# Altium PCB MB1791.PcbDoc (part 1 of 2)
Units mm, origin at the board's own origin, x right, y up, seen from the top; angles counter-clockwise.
Board outline 68.69 x 34.35 mm, 2 copper layers (Top Layer, Bottom Layer), stack 0.78 mm thick; 94 components, 70 nets, 269 pads, 1128 vias.
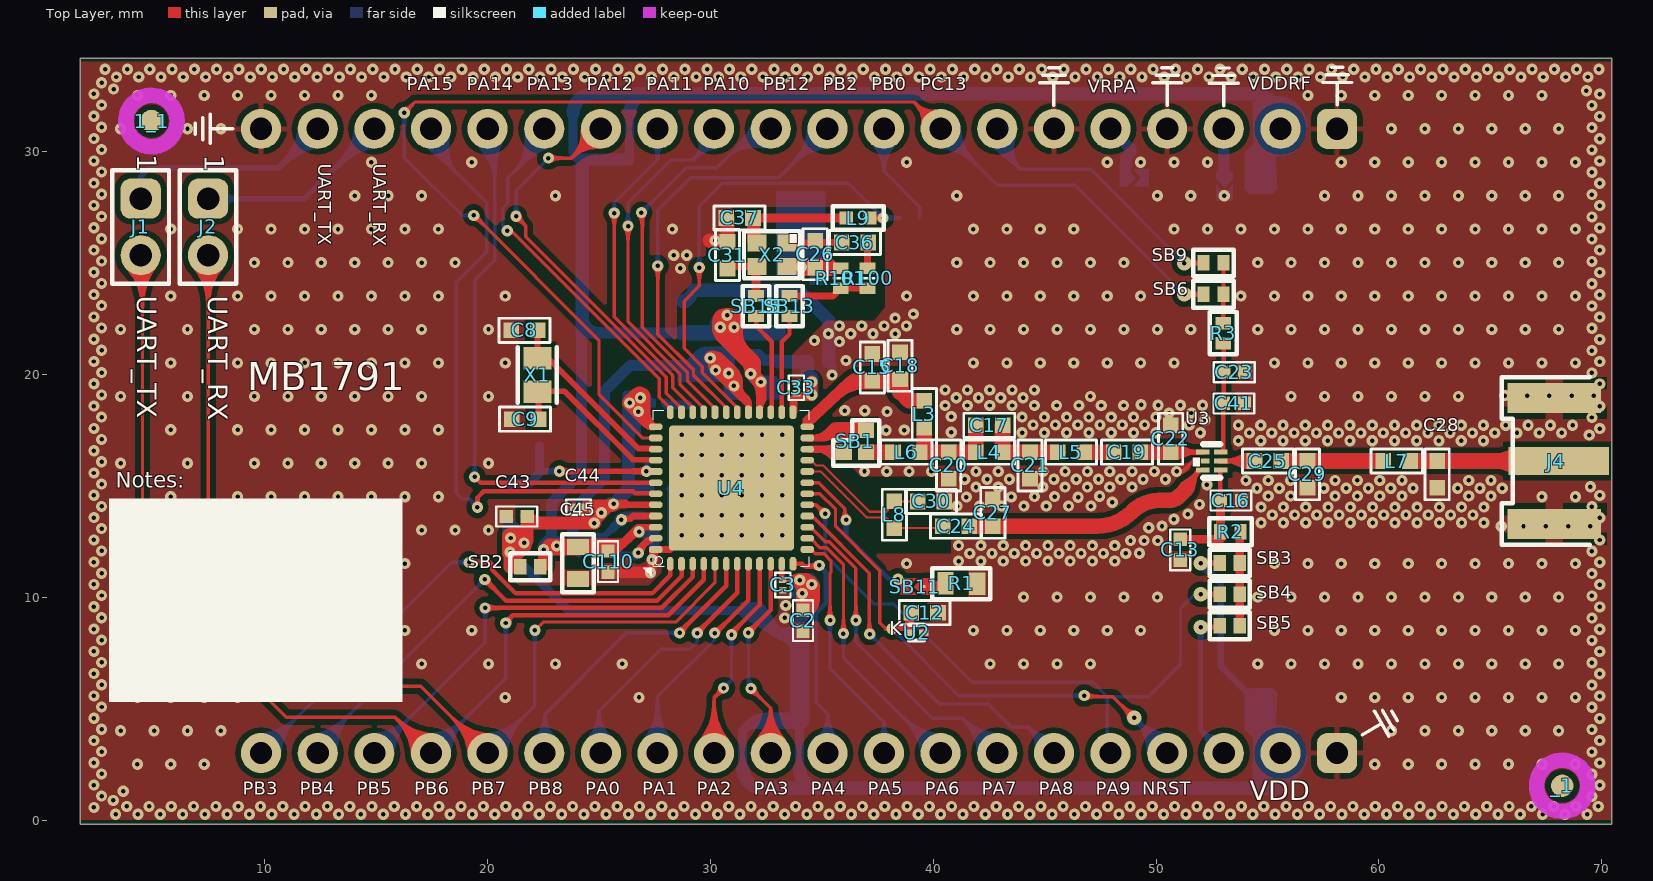
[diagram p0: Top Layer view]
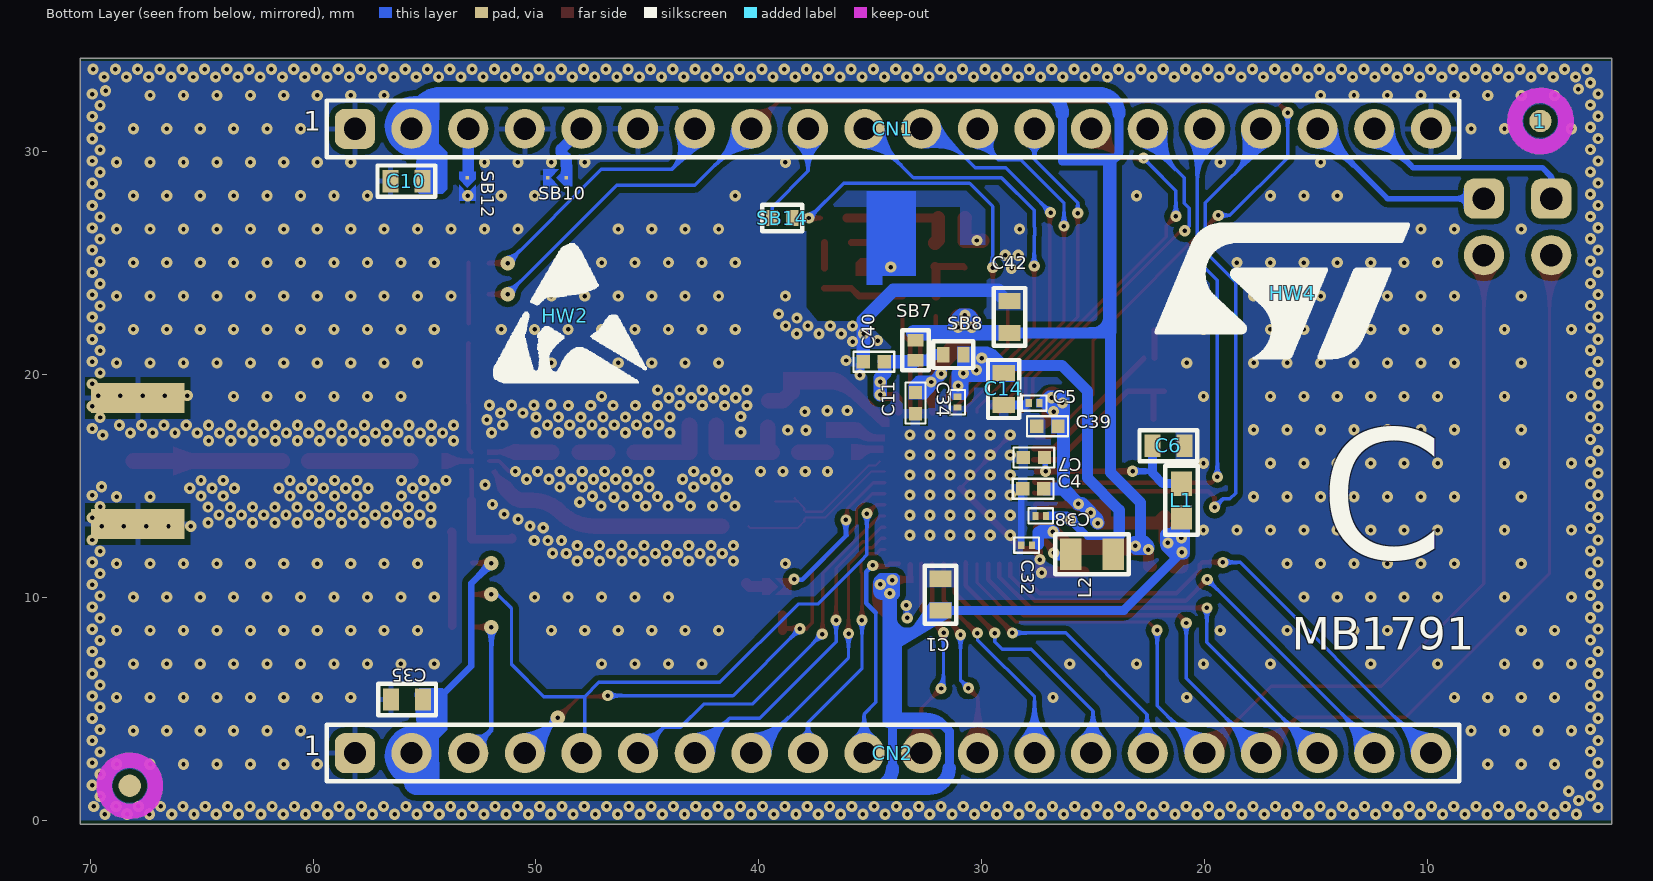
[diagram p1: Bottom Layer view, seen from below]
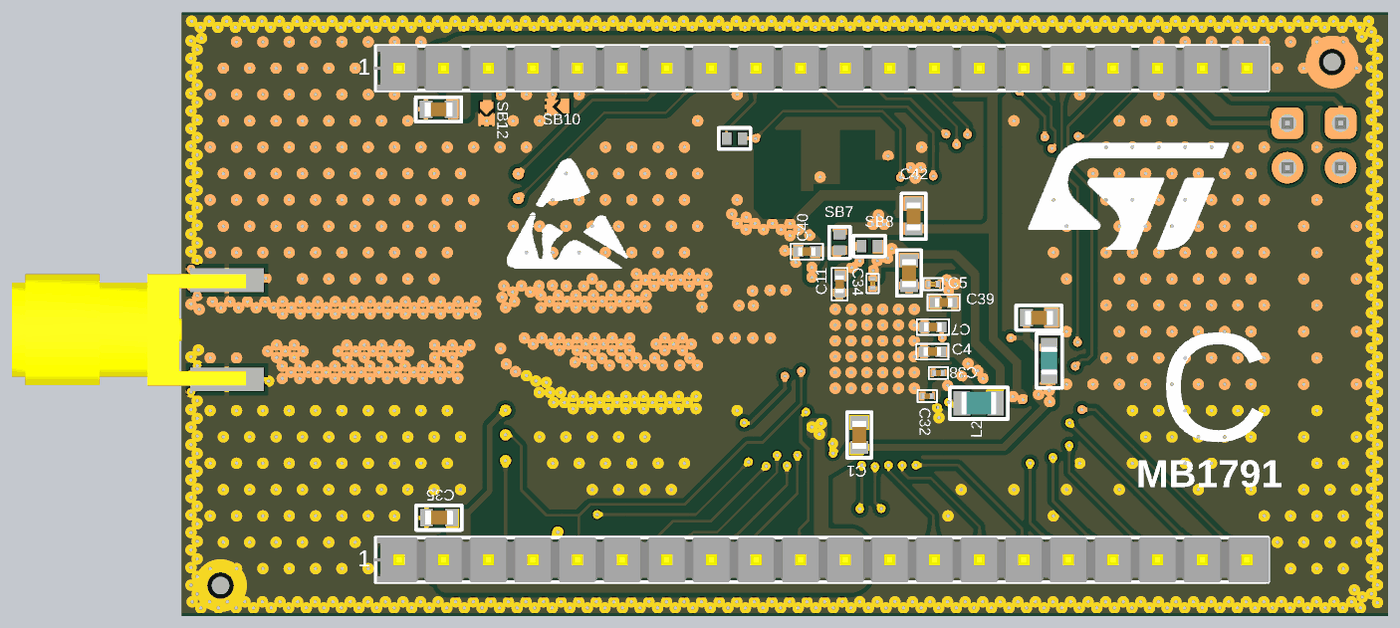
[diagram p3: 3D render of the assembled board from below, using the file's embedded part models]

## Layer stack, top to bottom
Top Solder: solder mask 0.01, Solder Resist, Dk 3.5
Top Layer: signal copper 0.035
Dielectric 1: core 0.71, FR-4, Dk 5
Bottom Layer: signal copper 0.035
Bottom Solder: solder mask 0.01, Solder Resist, Dk 3.5

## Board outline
1.751,-0.171 1.751,34.183 70.439,34.183 70.439,-0.171

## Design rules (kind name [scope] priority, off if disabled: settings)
BoardOutlineClearance [All] p1 off: gap=0.6 ignorepadtopadclearanceinfootprint=FALSE
Clearance Clearance_GND_50ohm [InNetClass('50Ohm') vs InNamedPolygon('TOP_LAYER_GND')] p1: gap=0.25 ignorepadtopadclearanceinfootprint=TRUE except(0.24: Arc-Fill Arc-Poly Arc-Region Track-Fill Track-Poly Track-Region)
Clearance Clearance_tab [(ObjectKind = 'Pad') And (Name Like 'Tab*-*') vs OnLayer('Keep-Out Layer')] p2: gap=0 ignorepadtopadclearanceinfootprint=TRUE
Clearance Clearance_via_to_via [(ObjectKind = 'Via') And (Net <> 'GND') vs (ObjectKind = 'Via') And (Net <> 'GND')] p3: gap=0.25 ignorepadtopadclearanceinfootprint=TRUE
Clearance "Clearance_Polygon to All" [InPolygon] p4: gap=0.25 ignorepadtopadclearanceinfootprint=TRUE
Clearance [All] p5: gap=0.1 ignorepadtopadclearanceinfootprint=TRUE
ComponentClearance [All] p1: gap=0 collisioncheckmode=3 verticalgap=0.1 showdistances=FALSE
DiffPairsRouting [InDifferentialPair('RFI')] p1: maxlimit=0.165 minlimit=0.164 mostfreqgap=0.164 toplayer_minwidth=0.1 toplayer_maxwidth=0.1 toplayer_prefwidth=0.1 bottomlayer_minwidth=0.1 bottomlayer_maxwidth=0.1 bottomlayer_prefwidth=0.1 maxuncoupledlength=12.7
HoleSize [All] p1: absolutevalues=TRUE maxlimit=10 minlimit=0.025 maxpercent=80.000 minpercent=20.000
HoleToHoleClearance [All] p1: gap=0.25 allowstackedmicrovias=TRUE
MaximumViaCount MaximumViaCount_5 [InNet('GND')] p1: limit=1300
MaximumViaCount MaximumViaCount_4 [InNet('VDDRF1V55')] p2: limit=1000
MaximumViaCount MaximumViaCount_3 [InNet('VDDPA')] p3: limit=1000
MaximumViaCount MaximumViaCount_2 [InNet('VDDRF')] p4: limit=1000
MaximumViaCount MaximumViaCount_1 [InNet('VDD')] p5: limit=1000
MaximumViaCount [All] p6: limit=3
MinimumSolderMaskSliver [All] p1: minsoldermaskwidth=0.1
PlaneConnect [InNet('GND')] p1: planeconnectstyle=Relief reliefexpansion=0.508 reliefentries=4 reliefconductorwidth=0.21 reliefairgap=0.21
PolygonConnect PolygonConnect_6 [InNet('VDDRF1V55')] p1: connectstyle=Direct reliefconductorwidth=0.254 reliefentries=4 polygonreliefangle="90 Angle" airgapwidth=0.254
PolygonConnect PolygonConnect_5 [InNet('VDDRF1V55')] p2: connectstyle=Direct reliefconductorwidth=0.254 reliefentries=4 polygonreliefangle="90 Angle" airgapwidth=0.254
PolygonConnect PolygonConnect_4 [InNet('vDDRF')] p3: connectstyle=Direct reliefconductorwidth=0.254 reliefentries=4 polygonreliefangle="90 Angle" airgapwidth=0.254
PolygonConnect PolygonConnect_3 [InNet('VDDPA')] p4: connectstyle=Direct reliefconductorwidth=0.254 reliefentries=4 polygonreliefangle="90 Angle" airgapwidth=0.254
PolygonConnect PolygonConnect_1 [InNet('VDDRF1V55')] p5: connectstyle=Direct reliefconductorwidth=0.254 reliefentries=4 polygonreliefangle="90 Angle" airgapwidth=0.254
PolygonConnect [InNet('VDD')] p6: connectstyle=Direct reliefconductorwidth=0.254 reliefentries=4 polygonreliefangle="90 Angle" airgapwidth=0.254
PolygonConnect PolygonConnect_VRPA [InNet('VRPA')] p7: connectstyle=Direct reliefconductorwidth=0.254 reliefentries=4 polygonreliefangle="90 Angle" airgapwidth=0.254
PolygonConnect PolygonConnect_RF [(ObjectKind = 'Pad') And (Name = 'C30-1')           or (ObjectKind = 'Pad') And (Name = 'C27-1')] p8: connectstyle=Direct reliefconductorwidth=0.254 reliefentries=4 polygonreliefangle="90 Angle" airgapwidth=0.254
PolygonConnect PolygonConnect_J1 [(ObjectKind = 'Pad') And (Name = 'J1-2')] p9: connectstyle=Direct reliefconductorwidth=0.254 reliefentries=4 polygonreliefangle="90 Angle" airgapwidth=0.254
PolygonConnect PolygonConnect_All [All] p10: thpad.connectstyle=Relief thpad.reliefconductorwidth=0.25 thpad.reliefentries=4 thpad.polygonreliefangle="90 Angle" thpad.airgapwidth=0.25 smdpad.connectstyle=Relief smdpad.reliefconductorwidth=0.25 smdpad.reliefentries=4 smdpad.polygonreliefangle="90 Angle" smdpad.airgapwidth=0.25 via.connectstyle=Direct via.reliefconductorwidth=0.2 via.reliefentries=4 via.polygonreliefangle="90 Angle" via.airgapwidth=0.25
RoutingLayers "RoutingLayers_90 Ohms" [InDifferentialPairClass('All Differential Pairs')] p1: top layer_v5=TRUE bottom layer_v5=TRUE
RoutingLayers [All] p2: top layer_v5=TRUE bottom layer_v5=TRUE
RoutingVias RoutingVias_BGA [InDrillLayerPair('Top Layer - MidLayer 1')] p1: holewidth=0.125 width=0.25 viastyle="Through Hole" minholewidth=0.125 minwidth=0.25 maxholewidth=0.125 maxwidth=0.3
RoutingVias [All] p2: holewidth=0.2 width=0.65 viastyle="Through Hole" minholewidth=0.2 minwidth=0.5 maxholewidth=0.2 maxwidth=0.7
ShortCircuit [(ObjectKind = 'Via') And (DrillPair = 'Top Layer - MidLayer 1') vs Ispad] p1: allowed=TRUE
SilkToSilkClearance [All] p1: silktosilkclearance=0.08
SilkToSolderMaskClearance [IsPad] p1: minsilkscreentomaskgap=0.08 clearancetoexposedcopper=TRUE
SolderMaskExpansion SolderMaskExpansion_VIA [IsVia] p1: expansion=-0.2 istentingtop=FALSE
SolderMaskExpansion [All] p2: expansion=0.075 istentingtop=FALSE
Width Width_RFI [InNet('RFI_N') and InNet('RFI_P')] p1: maxlimit=0.164 minlimit=0.164 preferedwidth=0.164
Width Width_50Ohms [InNetClass('50Ohms')] p2: maxlimit=0.7 minlimit=0.14 preferedwidth=0.5 bottomlayer_minwidth=0.2 bottomlayer_maxwidth=0.5 minimp=50.000000 maximp=50.000000 favimp=50.000000
Width [All] p3: maxlimit=1.5 minlimit=0.097 preferedwidth=0.15 bottomlayer_minwidth=0.1 minimp=50.000000 maximp=50.000000 favimp=50.000000
20 further rules are at their usual default settings.

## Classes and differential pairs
net class 50ohm: NetC17_1 NetC17_2 NetC19_1 NetC19_2 NetC24_2 NetC25_1 NetC25_2 NetC28_1
component class Reference_Design_STM32WL_2L_RF_SW: C1 C2 C3 C4 C5 C6 C7 C8 C9 C10 C11 C12 C13 C14 C15 C16 C17 C18 C19 C20 C21 C22 C23 C24 C25 C26 C27 C28 C29 C30 C31 C32 C33 C34 C35 C36 C37 C38 C39 C40 C41 C42 C43 C44 C45 C110 CN1 CN2 J1 J2 J4 L1 L2 L3 L4 L5 L6 L7 L8 L9 R1 R2 R3 R100 R101 S1 SB1 SB2 SB3 SB4 SB5 SB6 SB7 SB8 SB9 SB10 SB11 SB12 SB13 SB14 SB15 U2 U3 U4 X1 X2
differential pair RFI: +RFI_P -RFI_N

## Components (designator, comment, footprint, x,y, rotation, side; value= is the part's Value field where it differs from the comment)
1 "Comment" MIRE 4.947,31.37 r180 bottom
1_1 "Comment" MIRE 4.947,31.37 r0 top
_1 "Comment" MIRE 68.219,1.553 r0 top
C1 "" CAPC1608X09N 31.859,10.131 r270 bottom value=4.7uF
C2 "" CAPC1005X06N 34.166,8.958 r90 top value=100nF
C3 "" 0201 33.26,10.32 r90 top value=33pF
C4 "" CAPC1005X06N 27.7,14.876 r180 bottom value=100nF
C5 "" 0201 27.894,18.718 r180 bottom value=33pF
C6 "" CAPC1608X09N 21.632,16.806 r180 bottom value=4.7uF
C7 "" CAPC1005X06N 27.667,16.276 r0 bottom value=100nF
C8 "Capacitor" 0402 22.273,21.98 r180 top value=6.8pF
C9 "Capacitor" 0402 22.3,18 r180 top value=6.8pF
C10 "" CAPC1608X09N 55.809,28.675 r0 bottom value=4.7uF
C11 "" CAPC1005X06N 32.98,18.72 r270 bottom value=100nF
C12 "" 0402 39.025,9.32 r0 top value=100nF
C13 "" CAPC1005X06N 51.085,12.137 r90 top value=1nF
C14 "" CAPC1608X09N 29.026,19.35 r270 bottom value="0.47 uF"
C15 "" 0402 37.279,19.721 r90 top value="47 nF"
C16 "" CAPC1005X06N 53.358,14.348 r180 top value="10 pF"
C17 "" 0402 41.92,17.72 r0 top
C18 "" 0402 38.519,20.991 r270 top value="68 pF"
C19 "" 0402 49.294,16.52 r180 top
C20 "" 0402 40.702,16.519 r270 top
C21 "" 0402 44.349,15.323 r90 top
C22 "" 0402 50.655,17.717 r270 top
C23 "" CAPC1005X06N 53.509,20.104 r180 top value=1nF
C24 "" 0402 40.433,13.197 r0 top
C25 "" 0402_2 54.38,16.12 r0 top value="68 pF"
C26 "Capacitor" 0402 34.715,25.991 r270 top value=NM
C27 "NC" 0402_2 42.681,14.43 r270 top value=(0402)
C28 "MCD-00102" 0402 62.607,16.12 r270 top value="3.3 pF"
C29 "MCD-00102" 0402 56.792,16.12 r270 top value="3.3 pF"
C30 "" 0402 40.509,14.307 r180 top
C31 "Capacitor" 0402 30.778,24.758 r90 top value=NM
C32 "" 0201 28.234,12.343 r180 bottom value=33pF
C33 "" 0201 33.873,19.645 r270 top value=33pF
C34 "" 0201 31.1,18.521 r90 bottom value=33pF
C35 "" CAPC1608X09N 55.784,5.421 r180 bottom value=4.7uF
C36 "" 0402 37.093,25.92 r180 top value=0Ohm
C37 "" 0402 30.725,27.02 r0 top value="0 Ohm"
C38 "" 0201 27.12,13.66 r0 bottom value=33pF
C39 "" CAPC1005X06N 27.059,17.677 r0 bottom value=100nF
C40 "" CAPC1005X06N 34.847,20.576 r0 bottom value=100nF
C41 "" CAPC1005X06N 53.494,18.704 r0 top value="10 pF"
C42 "" CAPC1608X09N 28.764,22.581 r90 bottom value=4.7uF
C43 "" CAPC1005X06N 21.328,13.631 r0 top value=100nF
C44 "" 0201 23.857,14.051 r0 top value=33pF
C45 "" CAPC1608X09N 24.071,11.544 r270 top value=4.7uF
C110 "" CAPC1005X06N 25.421,11.608 r270 top value=100nF
CN1 "CON20" CO_SAMTEC_TSW-120-07-X-S 33.99,31.02 r180 bottom
CN2 "CON20" CO_SAMTEC_TSW-120-07-X-S 33.99,3.02 r180 bottom
Designator1 "Comment" Sheetbox_4L2S 1.774,-32.717 r0 top
Designator1 "Comment" PCB_SPECIFICATIONS 1.82,43.015 r0 top
Designator16 "Comment" IMPEDANCE_TABLE 1.904,81.221 r0 top
HW2 "Logo" LOGO_MAIN 48.68,22.632 r180 bottom value="LOGO ESD"
HW4 "Logo" LOGO_ST 16.06,23.64 r180 bottom value="LOGO ST"
J1 "HEADER_1X2_L" CO_MOLEX_22-03-2021 4.46,26.62 r270 top
J2 "HEADER_1X2_L" CO_MOLEX_22-03-2021 7.485,26.618 r270 top
J4 "SMA_T_9.52_NF" CO_SAMTEC_SMA-J-P-ST-EMI 69.96,16.12 r90 top
L1 "" INDC1608X95N 21.046,14.358 r90 bottom value=600R@100MHz
L2 "" INDC2012X13N 25.06,11.94 r0 bottom value="15 uH"
L3 "" 0402_COIL 39.607,18.221 r270 top
L4 "" 0402_COIL 42.513,16.52 r0 top
L5 "" 0402_COIL 46.184,16.52 r0 top
L6 "" 0402_COIL 38.802,16.52 r0 top
L7 "" 0402_COIL 60.795,16.12 r0 top
L8 "" 0402_COIL 38.264,13.713 r90 top
L9 "ferrite" IND_MURATA_LQW15A 36.64,27.02 r0 top value=LQW15AN3N9B00#
R1 "" RESC1608X05N 41.273,10.62 r180 top value=10K
R2 "" RESC1005X04N 53.336,12.948 r0 top value=100R
R3 "" RESC1005X04N 53.014,21.854 r90 top value=100R
R100 "Resistor" R0402 37.06,24.32 r90 top value=0
R101 "Resistor" R0402 35.86,24.32 r90 top value=NM
SB1 "SB_3Pads" SB3PADS_0402 36.982,17.037 r90 top
SB2 "Open" SB_0402 21.936,11.381 r180 top
SB3 "Close" SB_0402 53.304,11.548 r0 top value="0 ohm"
SB4 "Open" SB_0402 53.304,10.148 r0 top
SB5 "Open" SB_0402 53.304,8.734 r0 top
SB6 "Close" SB_0402 52.577,23.604 r0 top value="0 ohm"
SB7 "Open" SB_0402 32.98,21.093 r90 bottom
SB8 "Close" SB_0402 31.279,20.893 r0 bottom value=0
SB9 "Open" SB_0402 52.577,25.005 r0 top
SB10 "Close" GC_0402 49.018,28.825 r0 bottom
SB11 "Close" GC_0402 39.21,10.489 r180 top
SB12 "Close" GC_0402 53.077,28.451 r270 bottom
SB13 "Close" SB_0402 33.56,23.07 r90 top value=0
SB14 "Open" SB_0402 38.96,27.02 r0 bottom
SB15 "Close" SB_0402 32.06,23.07 r90 top value=0
U2 "" DIOM0603X03N 39.26,8.42 r0 top
U3 "BGS12SN6" SON40P70X40-6N 52.5,16.12 r0 top
U4 "STM32WLxx_QFN48" STM32WLXX_QFN48 30.957,14.903 r90 top
X1 "XTAL_2_PINS" OSC_NDK_NX2012SA 22.255,19.982 r90 top value=32.768KHz
X2 "" OSC_NDK_NX2016SA 32.77,25.373 r180 top value=32MHz
? "Comment" MIRE 68.219,1.553 r180 bottom

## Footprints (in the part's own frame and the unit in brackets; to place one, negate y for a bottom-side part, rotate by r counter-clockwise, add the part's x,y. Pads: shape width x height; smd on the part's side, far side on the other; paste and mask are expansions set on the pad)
0201 [mm]
  rect 0.28x0.35 smd: 1(0,0) 2(0.48,0)
  silkscreen extent -0.31,-0.34 0.79,0.34, body extent -0.06,-0.15 0.54,0.15, height 0.3
0402 [mm] "Chip Capacitor, Body 1.0x0.5mm, IPC High Density"
  rect 0.7x0.7 smd: 1(-0.001,0) 2(1.197,0)
  silkscreen extent -0.54,-0.54 1.74,0.54, body extent -0.42,-0.36 1.62,0.36, height 0.82
0402_2 [mm]
  rect 0.7x0.7 smd: 1(0.035,0) 2(1.233,0)
  silkscreen extent -0.51,-0.54 1.78,0.54, body extent -0.38,-0.36 1.65,0.36, height 0.82
0402_COIL [mm] "Coil FootPrint 0402"
  rect 0.7x0.7 smd: 1(-0.599,0) 2(0.599,0)
  silkscreen extent -1.15,-0.54 1.14,0.54, body extent -0.5,-0.3 0.5,0.3, height 0.51
CAPC1005X06N [mm]
  rect 0.6x0.6 smd: 1(-0.475,0) 2(0.475,0)
  silkscreen extent -0.92,-0.45 0.92,0.45, body extent -0.5,-0.25 0.5,0.25, height 0.6
CAPC1608X09N [mm]
  rect 0.725x1 smd: 1(-0.713,0) 2(0.713,0)
  Top Layer pour cut-out: -0.3,0.7 0.3,0.7 0.3,-0.7 -0.3,-0.7
  silkscreen extent -1.3,-0.7 1.3,0.7, body extent -0.8,-0.4 0.8,0.4, height 0.9
CO_MOLEX_22-03-2021 [mm]
  rrect50% 1.8x1.8 hole 1: 1(-1.27,0)
  round 1.8 hole 1: 2(1.27,0)
  silkscreen extent -2.54,-1.27 2.54,1.27, body extent -2.41,-1.18 2.41,1.18, height 10.79
CO_SAMTEC_SMA-J-P-ST-EMI [mm] "SMA Jack CMS, Edge Mountt Receptacle 50Ohm, 5-Leads, Body 6.35x6.35x9.52mm, pitch 2.825mm"
  rect 1.27x4.5 smd mask+0.05: 1(0,1.9)
  rect 1.35x4.2 smd mask+0.05: 2(-2.825,2.1) 2(2.825,2.1)
  rect 1.35x4.2 smd far side mask+0.05: 2(-2.825,2.1) 2(2.825,2.1)
  silkscreen extent -3.75,0.5 3.75,4.45, body extent -3.17,-10.13 3.17,3.2, height 3.8
CO_SAMTEC_TSW-120-07-X-S [mm] "Header, 20-Leads, 50.80x2.54x10.80mm, Pitch 2.54mm"
  rrect50% 1.8x1.8 hole 1: 1(-24.13,0)
  round 1.8 hole 1: 2(-21.59,0) 3(-19.05,0) 4(-16.51,0) 5(-13.97,0) 6(-11.43,0) 7(-8.89,0) 8(-6.35,0) 9(-3.81,0) 10(-1.27,0) 11(1.27,0) 12(3.81,0) 13(6.35,0) 14(8.89,0) 15(11.43,0) 16(13.97,0) 17(16.51,0) 18(19.05,0) 19(21.59,0) 20(24.13,0)
  silkscreen extent -25.4,-1.27 25.4,1.27, body extent -25.46,-1.27 25.46,1.27, height 8.38
DIOM0603X03N [mm] "Molded Diode, 2-Leads, Body 0.60x0.30mm"
  rect 0.425x0.3 smd: 1(-0.312,0) 2(0.313,0)
  silkscreen extent -0.32,-0.35 0.33,0.35, body extent -0.32,-0.18 0.33,0.18, height 0.33
GC_0402 [mm] "Grain de café format 0402"
  rect 0.15x0.15 smd paste-1: 1(-0.375,0) 2(0.45,0)
  Top Layer region: -0.65,0.375 -0.3,0.375 0.075,0 -0.3,-0.375 -0.65,-0.375
  Top Layer region: -0.05,0.375 0.65,0.375 0.65,-0.375 -0.05,-0.375 0.325,0
  body extent -0.5,-0.25 0.6,0.25, height 0.2
IMPEDANCE_TABLE [mm]
IND_MURATA_LQW15A [mm] "Inductor 2-Leads,Body 1.10x0.70x0.60mm(max)"
  rect 0.6x0.6 smd: 1(-0.53,0) 2(0.53,0)
  silkscreen extent -1.14,-0.53 1.14,0.53, body extent -0.5,-0.3 0.5,0.3, height 0.51
INDC1608X95N [mm] "Chip Inductor, 2-Leads, Body 1.75x0.95x0.95mm (0603)"
  rect 1.1x0.95 smd: 1(-0.75,0) 2(0.75,0)
  silkscreen extent -1.55,-0.72 1.55,0.72, body extent -0.8,-0.48 0.8,0.47, height 0.8
INDC2012X13N [mm] "Chip Inductor, 2-Leads, Body 2.0x1.2x1.3 (0805)"
  rect 0.96x1.4 smd: 1(-0.952,0) 2(0.952,0)
  silkscreen extent -1.65,-0.9 1.65,0.9, body extent -1,-0.65 1,0.65, height 1.18
LOGO_MAIN [mm]
  silkscreen extent -3.24,-3.02 3.65,3.22
LOGO_ST [mm]
  silkscreen extent -6.18,-2.95 5.25,3.14
MIRE [mm] "Fiducial Target Round , Pad 1.0mm, Keepout 3mm"
  round 1 smd mask+1: 1(0,0)
  Top Layer keep-out circle w0.7: c0,0 r1.15
  body extent -0.5,-0.5 0.5,0.5, height 0.04
OSC_NDK_NX2012SA [mm] "Crystal, 2-Leads, Body 2.05x1.20x0.55mm (Tol:-/+0.05)"
  rect 1x1.25 smd: 1(-0.75,0) 2(0.75,0)
  silkscreen extent -1.25,-0.87 1.25,0.87, body extent -1.04,-0.63 1.03,0.63, height 0.55
OSC_NDK_NX2016SA [mm] "Crystal, 4-Leads, Body 2.10x1.61x0.50mm (max), Pitch 1.35x1.05mm"
  rect 0.85x0.75 smd: 1(-0.675,-0.525) 2(0.675,-0.525) 3(0.675,0.525) 4(-0.675,0.525)
  silkscreen extent -1.25,-1.05 1.25,1.05, body extent -1,-0.8 1,0.8, height 0.5
PCB_SPECIFICATIONS [mm]
R0402 [mm]
  rect 0.51x0.7 smd mask+0.05: 1(-0.45,0) 2(0.45,0)
  silkscreen extent 0,-0.3 0,0.3, body extent -0.52,-0.3 0.52,0.3, height 0.4
RESC1005X04N [mm] "Chip Resistor, 2-Leads, Body 1.00x0.50mm (0402)"
  rect 0.55x0.7 smd: 1(-0.45,0) 2(0.45,0)
  silkscreen extent -0.95,-0.6 0.95,0.6, body extent -0.5,-0.25 0.5,0.25, height 0.35
RESC1608X05N [mm] "Chip Resistor, 2-Leads, Body 1.60x0.80mm (0603)"
  rect 0.725x1 smd: 1(-0.713,0) 2(0.712,-0.016)
  Top Layer pour cut-out: -0.3,0.7 0.3,0.7 0.3,-0.7 -0.3,-0.7
  silkscreen extent -1.3,-0.7 1.3,0.7, body extent -0.77,-0.42 0.78,0.43, height 0.45
SB3PADS_0402 [mm] "Solder Bridge 0 Ohm (0402)"
  rect 0.7x0.7 smd: 1(0.466,-0.009) 2(-0.517,-0.009) 3(-0.517,0.974)
  silkscreen extent -1.13,-0.61 0.91,1.46, body extent -0.79,-0.05 -0.29,0.95, height 0.25
SB_0402 [mm]
  rect 0.55x0.7 smd: 1(-0.45,0) 2(0.45,0)
  silkscreen extent -0.9,-0.6 0.9,0.6, body extent -0.5,-0.25 0.5,0.25, height 0.25
Sheetbox_4L2S [mil] "Sheetbox 4 layers / 2 silkscreens"
  round 20 on Mech16: 1(813.78,210.69) 1(2736.9,210.69)
SON40P70X40-6N [mm] "SON, 6-Leads, Body 1.10x0.70mm, Pitch 0.40mm"
  rect 0.6x0.225 smd: 1(-0.4,0.4) 2(-0.4,0) 3(-0.4,-0.4) 4(0.4,-0.4) 5(0.4,0) 6(0.4,0.4)
  silkscreen extent -0.38,-0.75 0.38,0.75, body extent -0.38,-0.58 0.38,0.58, height 0.4
STM32WLXX_QFN48 [mm] "QFN48 7x7x0.55mm pitch 0.5mm"
  oct 0.6x0.3 smd mask+0.06: 1(-3.398,2.746) 2(-3.398,2.239) 3(-3.398,1.739) 4(-3.398,1.239) 5(-3.398,0.739) 6(-3.398,0.239) 7(-3.398,-0.261) 8(-3.398,-0.761) 9(-3.398,-1.261) 10(-3.398,-1.761) 11(-3.398,-2.261) 12(-3.398,-2.761) 25(3.398,-2.761) 26(3.398,-2.261) 27(3.398,-1.761) 28(3.398,-1.261) 29(3.398,-0.761) 30(3.398,-0.261) 31(3.398,0.239) 32(3.398,0.739) 33(3.398,1.239) 34(3.398,1.739) 35(3.398,2.239) 36(3.398,2.739)
  oct 0.3x0.6 smd mask+0.06: 13(-2.752,-3.399) 14(-2.252,-3.399) 15(-1.752,-3.399) 16(-1.252,-3.399) 17(-0.752,-3.399) 18(-0.252,-3.399) 19(0.248,-3.399) 20(0.748,-3.399) 21(1.248,-3.399) 22(1.748,-3.399) 23(2.248,-3.399) 24(2.748,-3.399) 37(2.748,3.399) 38(2.248,3.399) 39(1.748,3.399) 40(1.248,3.399) 41(0.748,3.399) 42(0.248,3.399) 43(-0.252,3.399) 44(-0.752,3.399) 45(-1.252,3.399) 46(-1.752,3.399) 47(-2.252,3.399) 48(-2.752,3.399)
  rrect5% 5.6x5.6 smd paste-3 mask+0.08: 49(0,0)
  silkscreen extent -3.95,-3.5 3.5,3.96, body extent -3.51,-3.51 3.51,3.51, height 0.78

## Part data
C1 C6 C10 C35 C42 C45: library part MCD-00009, "Capacitor, MLCC, 4.7uF, 16V, X5R, 10%, 0603, T=0.8mm", Manufacturer=YAGEO, Manufacturer_Part_Number=CC0603KRX5R7BB475, Package=C0603
C2 C3 C4 C5 C7 C11 C12 C39 C40 C43 C44 C110: library part MCD-00102, "Capacitor, MLCC, 100nF, 16V, X7R, 10%, 0402, T=0,5mm", Manufacturer=YAGEO, Manufacturer_Part_Number=CC0402KRX7R7BB104, Package=C0402
C8 C9 C26 C31: library part MCD-00003, "Capacitor, MLCC, 6.8pF, 50V, NPO, +-0.1pF, 0402, T=0.5mm", Manufacturer=MURATA, Manufacturer_Part_Number=GRM1555C1H6R8BA01
C13 C23: library part MCD-00198, "Capacitor, MLCC, 1nF, 16V, X7R, 10%, 0402, T=0.5mm", Manufacturer=YAGEO, Manufacturer_Part_Number=CC0402KRX7R7BB102
C14: library part MCD-00009, "Capacitor, MLCC, 4.7 uF, 16V, X5R, 10%, 0603, T=0.8mm", Manufacturer=YAGEO, Manufacturer_Part_Number=CC0603KRX5R7BB474, Package=C0603
C15: library part MCD-01123, "Capacitor, MLCC,47nF, 16V, X7R, 10%, 0402, T=0.5mm", Manufacturer=MURATA, Manufacturer_Part_Number=GCM155R71E473KA55
C16 C41: library part MCD-00102, "Capacitor, MLCC, 10 pF", Manufacturer=MURATA, Manufacturer_Part_Number=GJM1555C1H100FB01D, Package=C0402
C17: library part MCD-01123
C18 C38: library part MCD-01123, "Capacitor, MLCC,68pF, 50V, C0G, 1%, 0402, T=0.5mm", Manufacturer=MURATA, Manufacturer_Part_Number=GCM1555C1H680JA16
C19: library part MCD-01123, "Condensateurs céramique multicouches MLCC - CMS 33PF 50V 2% 0402"
C20: library part MCD-00102, "N/C", Manufacturer=Murata, Manufacturer_Part_Number="Not Connected", Package=C0402
C21: library part MCD-00015, "Condensateurs céramique multicouches MLCC - CMS 0402 3.3pF 50Volts C0G +/-0.05pF"
C22: library part MCD-01123, "Condensateurs céramique multicouches MLCC - CMS 0402 2.7 pF 50Volts C0G +/-0.25pF"
C24: library part MCD-01123, "Condensateurs céramique multicouches MLCC - CMS 0402 3.6pF 50Volts C0G +/-0.05pF", Manufacturer=MURATA, Manufacturer_Part_Number=GJM1555C1H3R6WB01D
C25: library part MCD-01123, "Multilayer Ceramic Capacitors MLCC - SMD/SMT 0402 68pF 50volts C0G 5%", Manufacturer=MURATA, Manufacturer_Part_Number=GCM1555C1H680JA16
C27: library part MCD-01123, "Not connected [0402]", Manufacturer=MURATA
C28 C29: "Condensateurs céramique multicouches MLCC - CMS 0402 3.3pF 50Volts C0G +/-0.05pF", Manufacturer=MURATA, Manufacturer_Part_Number=GJM1555C1H3R3WB01D, Package=C0402
C30: library part MCD-01123, "Condensateurs céramique multicouches MLCC - CMS 0402 2.7pF 50Volts C0G +/-0.1pF", Manufacturer=MURATA, Manufacturer_Part_Number=GJM1555C1H2R7BB01D
C32 C33 C34 C36 C37: library part MCD-00277, "Capacitor, MLCC, 33pF, 50V, NPO, 2%, 0402, T=0,5mm", Manufacturer=MURATA, Manufacturer_Part_Number=GRM1555C1H330GA01
CN1 CN2: "Connector right-angle, pitch 2.54mm, 20 contacts", Manufacturer=SAMTEC, Manufacturer_Part_Number=TSW-120-07-L-S
Designator16: library part MCD-00279
HW2: library part MCD-00627, "\"Hand\" ESD logo footprint for PCB"
HW4: library part MCD-00625, "\"STMicroelectronics\" logo footprint for PCB"
J4: "SMA Jack, Edge Mount, 50 Ohms", Manufacturer=SAMTEC, Manufacturer_Part_Number=SMA-J-P-H-ST-EM1
L1: library part MCD-00047, "SMD Chip ferrite bead, 600R@100MHz +/-25%, 350mA, 500mohm DC, 0603, T=0.8mm", Manufacturer=TAI-TECH, Manufacturer_Part_Number=FCM1608KF-601T03
L2: library part MCD-01433, "MLZ2012 Multilayer Shielded Inductor 15 uH, ±5%", Manufacturer=TDK, Manufacturer_Part_Number=MLZ2012M150W
L3: library part MCD-01330, "Inductor, 68nH, +-0.1nH, 140mA, 0402"
L4 L6: library part MCD-01330, "Inductor, 8.2nH, +-0.2nH, 750mA, 0402"
L5: library part MCD-01330, "Inductor, 8.7nH, +-0.1nH, 540mA, 0402"
L7: library part MCD-01330, "Inductor, 15nH, +-0.1nH, 640mA, 0402"
L8: library part MCD-01330, "Inductor, 11 nH, +-0.1nH, 270mA, 0402", Manufacturer=MURATA, Manufacturer_Part_Number=LQW15AN11NG00D
L9: library part MCD-01330, "Inductor, 3.9nH, +-0.1nH, 750mA, 0402", Manufacturer=MURATA, Manufacturer_Part_Number=LQW15AN3N9B00#, Package=L0402
R1: library part MCD-00220, "Resistor,10K,0603,1%,1/10W", Manufacturer=YAGEO, Manufacturer_Part_Number=RC0603FR-0710KL
R2 R3: library part MCD-00119, "Resistor,100R,0402,1%,1/16W", Manufacturer=YAGEO, Manufacturer_Part_Number=RC0402FR-07100RL
R100 R101: library part MCD-00052, "Resistor,0R,0402,5%,1/16W", Manufacturer=YAGEO, Manufacturer_Part_Number=RC0402JR-070RL, Package=R0402
SB1: "Solder Bridge"
SB2 SB4 SB5 SB7 SB9 SB14: library part SB_Open, "Solder Bridge Open [0402] (Unpopulated)"
SB3 SB6 SB8 SB13 SB15: library part SB_0Ohm, "Solder Bridge 0R [0402] (Populated with 0 Ohm)", Manufacturer="Vishay / Dale", Manufacturer_Part_Number=RCS04020000Z0ED
SB10 SB12: library part Strap2, "Solder Jumper - Open"
SB11: library part Strap2, "Solder Jumper - Close"
U2: library part MCD-00170, "ESD protection 6V1", Manufacturer=STMICROELECTRONICS, Manufacturer_Part_Number=ESDALC6V1-1U2
U3: "DC switch - Ultra-Low  SPDT analog switch", Manufacturer=INFINEON
U4: "STM32WL ARM MCU Multiprotocol LPWAN 32-bit Arm Cortex-M4 MCUs LoRa (G)FSK-MSK BPSK", Manufacturer=STMicroelectronics, Manufacturer_Part_Number=STM32WLE5CC
X1: library part MCD-01479, "Crystal 32.768kHz, 6pF, -+20PPM, R=80K, SMD", Manufacturer=NDK, Manufacturer_Part_Number="NX2012SA 32.768KHz EXS00A-MU00527"
X2: library part MCD-01446, "Crystal 32 MHz, 8pF, -+10 PPM, R=60Ω, SMD", Manufacturer=NDK, Manufacturer_Part_Number="NX2016SA 32MHz EXS00A-CS06465"

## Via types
v1: diameter 0.5, hole 0.2, Top Layer to Bottom Layer, 1122 vias
v2: diameter 0.65, hole 0.2, Top Layer to Bottom Layer, 6 vias

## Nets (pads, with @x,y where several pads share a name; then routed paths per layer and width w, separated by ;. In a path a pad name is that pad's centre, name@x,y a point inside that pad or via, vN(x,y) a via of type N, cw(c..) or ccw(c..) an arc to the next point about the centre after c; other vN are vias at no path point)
FE_CTRL2: CN1.7 SB9.1 | length 12.2
  Top Layer w0.2: v2(51.274,25) SB9.1@52.122,25
  Bottom Layer w0.15: CN1.7@42.88,31.02 42.88,30.237 43.915,29.203 47.071,29.203 v2(51.274,25)
FE_CTRL3: CN2.3 SB5.1 | length 7
  Top Layer w0.2: v2(51.997,8.67) 52.791,8.67 SB5.1@52.854,8.734
  Bottom Layer w0.2: v2(51.997,8.67) 51.997,4.063 CN2.3@53.04,3.02
GND: C1.1 C2.1 C3.1 C4.1 C5.1 C6.2 C7.2 C8.2 C9.2 C10.2 C11.2 C12.2 C13.1 C14.2 C15.2 C16.1 C18.1 C20.2 C21.1 C22.1 C23.1 C26.2 C27.1 C28.2 C29.2 C30.1 C31.2 C32.1 C33.1 C34.1 C35.1 C37.1 C38.2 C39.2 C40.2 C41.2 C42.2 C43.1 C44.1 C45.2 C110.2 CN1.1 CN1.4 CN1.6 CN1.20 CN2.1 J4.2 R1.1 R101.2 SB10.2 SB12.2 U2.2 U3.2 U4.48 U4.49 X2.4 | length 28.7
  Top Layer w0.15: v1(28.728,17.29) 29.596,16.361 30.464,15.431 U4.49@30.957,14.903
  Top Layer w0.2: v1@27.324,11.157 v1@27.4,11.233 ; U4.48@27.558,12.152 U4.48@27.63,12.152 ; v1(50.925,15.651) 51.193,15.651 51.662,16.12 U3.2@52.1,16.12
  Top Layer w0.3: U4.48@27.63,12.152 28.206,12.152 U4.49@30.957,14.903
  Top Layer w0.4: v1(27.324,11.11) 27.4,11.187 27.4,11.233 v1(27.4,11.7) 27.46,11.76 U4.48@27.46,12.052
  Top Layer w0.5: C110.2@25.421,11.133 27.301,11.133 v1(27.324,11.11)
  Top Layer w0.625: 29.96,26.02 29.989,25.991 30.778,25.991 30.778,27.002 C37.1@30.76,27.02 ; C26.2@34.625,24.848 C26.2@34.715,24.758
  Bottom Layer w0.2: v1(33.35,9.084) 33.35,9.604 v1(33.39,9.644)
  Bottom Layer w0.3: C4.1@28.175,14.876 28.234,14.817 C32.1@28.234,12.343
  Bottom Layer w0.4: C5.1@27.971,18.729 28.063,18.638 C14.2@29.026,18.638 ; C42.2@28.764,23.294 29.252,23.782 ; C40.2@35.322,20.576 35.469,20.429 v1(35.469,19.973)
  Bottom Layer w0.6: C42.2@28.764,23.294 28.901,23.294 C42.2@29.128,23.52 ; 29.252,23.782 33.98,23.782 35.322,22.44 C40.2@35.322,20.576
  other v1: 3.338,0.28 4.338,0.28 5.338,0.28 6.338,0.28 7.338,0.28 8.338,0.28 9.338,0.28 10.338,0.28 11.338,0.28 12.338,0.28 13.338,0.28 14.338,0.28 15.338,0.28 16.338,0.28 17.338,0.28 18.338,0.28 19.338,0.28 20.338,0.28 21.338,0.28 22.338,0.28 23.338,0.28 24.338,0.28 25.338,0.28 26.338,0.28 27.338,0.28 28.338,0.28 29.338,0.28 30.338,0.28 31.338,0.28 32.338,0.28 33.338,0.28 34.338,0.28 35.338,0.28 36.338,0.28 37.338,0.28 38.338,0.28 39.338,0.28 40.338,0.28 41.338,0.28 42.338,0.28 43.338,0.28 44.338,0.28 45.338,0.28 46.338,0.28 47.338,0.28 48.338,0.28 49.338,0.28 50.338,0.28 51.338,0.28 52.338,0.28 53.338,0.28 54.338,0.28 55.338,0.28 56.338,0.28 57.338,0.28 58.338,0.28 59.338,0.28 60.338,0.28 61.338,0.28 62.338,0.28 63.338,0.28 64.338,0.28 65.338,0.28 66.338,0.28 67.338,0.28 68.338,0.28 69.338,0.28 2.359,0.584 3.834,0.63 4.834,0.63 5.834,0.63 6.834,0.63 7.834,0.63 8.834,0.63 9.834,0.63 10.834,0.63 11.834,0.63 12.834,0.63 13.834,0.63 14.834,0.63 15.834,0.63 16.834,0.63 17.834,0.63 18.834,0.63 19.834,0.63 20.834,0.63 21.834,0.63 22.834,0.63 23.834,0.63 24.834,0.63 25.834,0.63 26.834,0.63 27.834,0.63 28.834,0.63 29.834,0.63 30.834,0.63 31.834,0.63 32.834,0.63 33.834,0.63 34.834,0.63 35.834,0.63 36.834,0.63 37.834,0.63 38.834,0.63 39.834,0.63 40.834,0.63 41.834,0.63 42.834,0.63 43.834,0.63 44.834,0.63 45.834,0.63 46.834,0.63 47.834,0.63 48.834,0.63 49.834,0.63 50.834,0.63 51.834,0.63 52.834,0.63 53.834,0.63 54.834,0.63 55.834,0.63 56.834,0.63 57.834,0.63 58.834,0.63 59.834,0.63 60.834,0.63 61.834,0.63 62.834,0.63 63.834,0.63 64.834,0.63 65.834,0.63 66.834,0.63 67.834,0.63 68.834,0.63 69.834,0.63 3.228,0.899 69.55,1.073 2.708,1.088 3.679,1.307 2.359,1.584 69.9,1.577 2.708,2.088 69.55,2.073 4.31,2.52 5.81,2.52 7.31,2.52 59.81,2.52 61.31,2.52 62.81,2.52 64.31,2.52 65.81,2.52 67.31,2.52 68.81,2.52 2.359,2.584 69.9,2.577 69.55,3.073 2.708,3.088 2.359,3.584 69.9,3.577 3.56,4.02 5.06,4.02 6.56,4.02 8.06,4.02 60.56,4.02 62.06,4.02 63.56,4.02 65.06,4.02 66.56,4.02 68.06,4.02 69.55,4.073 2.708,4.088 69.9,4.577 2.359,4.584 2.708,5.088 69.55,5.073 4.31,5.52 5.81,5.52 7.31,5.52 8.81,5.52 20.81,5.52 26.81,5.52 58.31,5.52 59.81,5.52 61.31,5.52 62.81,5.52 64.31,5.52 65.81,5.52 67.31,5.52 68.81,5.52 2.359,5.584 69.9,5.577 69.55,6.073 2.708,6.088 2.359,6.584 69.9,6.577 3.56,7.02 5.06,7.02 6.56,7.02 9.56,7.02 12.56,7.02 17.06,7.02 20.06,7.02 23.06,7.02 26.06,7.02 42.56,7.02 44.06,7.02 45.56,7.02 47.06,7.02 54.56,7.02 56.06,7.02 57.56,7.02 59.06,7.02 60.56,7.02 62.06,7.02 63.56,7.02 65.06,7.02 66.56,7.02 68.06,7.02 69.55,7.073 2.708,7.088 69.9,7.577 2.359,7.584 2.708,8.088 69.55,8.073 4.31,8.52 5.81,8.52 11.81,8.52 13.31,8.52 16.31,8.52 19.31,8.52 41.81,8.52 43.31,8.52 44.81,8.52 46.31,8.52 47.81,8.52 49.31,8.52 55.31,8.52 56.81,8.52 58.31,8.52 59.81,8.52 61.31,8.52 62.81,8.52 64.31,8.52 65.81,8.52 67.31,8.52 68.81,8.52 2.359,8.584 69.9,8.577 69.55,9.073 2.708,9.088 2.359,9.584 69.9,9.577 3.56,10.02 6.56,10.02 9.56,10.02 11.06,10.02 12.56,10.02 14.06,10.02 15.56,10.02 44.06,10.02 45.56,10.02 47.06,10.02 48.56,10.02 50.06,10.02 54.56,10.02 56.06,10.02 57.56,10.02 59.06,10.02 60.56,10.02 62.06,10.02 63.56,10.02 65.06,10.02 66.56,10.02 68.06,10.02 2.708,10.088 69.55,10.073 69.9,10.577 2.359,10.584 69.55,11.073 2.708,11.088 5.81,11.52 8.81,11.52 10.31,11.52 11.81,11.52 13.31,11.52 14.81,11.52 16.31,11.52 38.81,11.52 55.31,11.52 56.81,11.52 58.31,11.52 59.81,11.52 61.31,11.52 62.81,11.52 64.31,11.52 65.81,11.52 67.31,11.52 68.81,11.52 2.359,11.584 69.9,11.577 41.147,11.628 42.147,11.628 43.147,11.628 44.147,11.628 45.147,11.628 46.147,11.628 47.147,11.628 48.147,11.628 41.643,11.977 42.643,11.977 43.643,11.977 44.643,11.977 45.643,11.977 46.643,11.977 47.643,11.977 48.643,11.977 49.257,11.98 69.55,12.073 2.708,12.088 41.147,12.327 42.147,12.327 43.147,12.327 44.147,12.327 45.147,12.327 46.147,12.327 47.147,12.327 48.147,12.327 48.856,12.553 49.462,12.551 50.076,12.554 2.359,12.584 69.9,12.577 28.728,12.79 29.628,12.79 30.528,12.79 31.428,12.79 32.328,12.79 33.228,12.79 3.56,13.02 6.56,13.02 9.56,13.02 11.06,13.02 12.56,13.02 14.06,13.02 15.56,13.02 17.06,13.02 18.56,13.02 20.06,13.02 2.708,13.088 49.675,13.127 50.269,13.203 65.482,13.196 66.482,13.196 67.482,13.196 68.482,13.196 69.482,13.196 54.717,13.353 55.717,13.353 56.717,13.353 57.717,13.353 58.717,13.353 59.717,13.353 60.717,13.353 61.708,13.353 62.708,13.353 63.708,13.353 64.708,13.353 50.806,13.506 2.359,13.584 69.9,13.577 28.728,13.69 29.628,13.69 30.528,13.69 31.428,13.69 32.328,13.69 33.228,13.69 55.212,13.703 56.212,13.703 57.212,13.703 58.212,13.703 59.212,13.703 60.212,13.703 61.212,13.703 62.212,13.703 63.212,13.703 64.212,13.703 51.428,13.741 54.717,14.052 55.717,14.052 56.717,14.052 57.717,14.052 58.717,14.052 59.717,14.052 60.717,14.052 61.708,14.052 62.708,14.052 63.708,14.052 64.708,14.052 69.55,14.073 2.708,14.088 41.076,14.099 42.076,14.099 43.076,14.099 44.076,14.099 45.076,14.099 46.076,14.099 47.076,14.099 51.951,14.173 48.038,14.273 41.498,14.501 43.505,14.509 46.508,14.493 5.81,14.52 8.81,14.52 10.31,14.52 11.81,14.52 13.31,14.52 14.81,14.52 16.31,14.52 17.81,14.52 44.55,14.521 45.451,14.526 67.31,14.52 68.81,14.52 47.471,14.542 55.034,14.55 56.034,14.55 58.034,14.55 59.034,14.55 60.034,14.55 61.034,14.55 64.025,14.55 65.025,14.55 2.359,14.584 28.728,14.59 29.628,14.59 30.528,14.59 31.428,14.59 32.328,14.59 33.228,14.59 69.9,14.577 54.529,14.899 55.529,14.899 57.529,14.899 58.529,14.899 59.529,14.899 60.529,14.899 61.529,14.899 63.529,14.899 64.529,14.899 65.529,14.899 41.925,14.952 42.925,14.952 44.925,14.952 45.925,14.952 46.925,14.952 47.925,14.952 48.925,14.952 69.481,14.968 52.279,15.059 2.708,15.088 54.034,15.249 55.034,15.249 56.034,15.249 58.034,15.249 59.034,15.249 60.034,15.249 61.034,15.249 64.025,15.249 65.025,15.249 41.421,15.301 42.421,15.301 43.421,15.301 45.421,15.301 46.421,15.301 47.421,15.301 48.421,15.301 49.421,15.301 50.421,15.301 28.728,15.49 29.628,15.49 30.528,15.49 31.428,15.49 32.328,15.49 33.228,15.49 2.359,15.584 36.925,15.651 37.925,15.651 38.925,15.651 39.925,15.651 41.925,15.651 42.925,15.651 44.925,15.651 45.925,15.651 46.925,15.651 47.925,15.651 48.925,15.651 49.925,15.651 3.56,16.02 6.56,16.02 9.56,16.02 11.06,16.02 12.56,16.02 14.06,16.02 15.56,16.02 17.06,16.02 20.06,16.02 2.708,16.088 28.728,16.39 29.628,16.39 30.528,16.39 31.428,16.39 32.328,16.39 33.228,16.39 2.359,16.584 53.696,17.028 54.696,17.028 55.696,17.028 56.696,17.028 57.696,17.028 58.696,17.028 59.696,17.028 60.696,17.028 61.687,17.028 62.687,17.028 63.687,17.028 64.687,17.028 2.708,17.088 69.434,17.281 29.628,17.29 30.528,17.29 31.428,17.29 32.328,17.29 33.228,17.29 54.192,17.378 55.192,17.378 56.192,17.378 57.192,17.378 58.192,17.378 59.192,17.378 60.192,17.378 61.192,17.378 62.192,17.378 63.192,17.378 64.192,17.378 65.192,17.378 66.192,17.378 67.192,17.378 68.192,17.378 43.992,17.387 44.992,17.387 45.992,17.387 46.992,17.387 47.992,17.387 48.992,17.387 49.992,17.387 51.992,17.387 40.813,17.411 37.893,17.499 38.709,17.504 5.81,17.52 8.81,17.52 10.31,17.52 11.81,17.52 13.31,17.52 14.81,17.52 16.31,17.52 17.81,17.52 2.359,17.584 69.9,17.577 44.488,17.737 45.488,17.737 46.488,17.737 47.488,17.737 48.488,17.737 49.488,17.737 51.488,17.737 53.696,17.727 54.696,17.727 55.696,17.727 56.696,17.727 57.696,17.727 58.696,17.727 59.696,17.727 60.696,17.727 61.687,17.727 62.687,17.727 63.687,17.727 64.687,17.727 65.687,17.727 66.687,17.727 67.687,17.727 68.687,17.727 52.199,17.97 2.708,18.088 43.992,18.087 44.992,18.087 45.992,18.087 46.992,18.087 47.992,18.087 48.992,18.087 49.992,18.087 69.55,18.073 40.813,18.11 50.587,18.274 51.587,18.274 37.937,18.336 36.939,18.372 36.042,18.379 69.9,18.577 2.359,18.584 40.543,18.609 41.543,18.609 42.543,18.609 43.543,18.609 44.543,18.609 45.543,18.609 46.543,18.609 47.543,18.609 48.543,18.609 50.091,18.624 51.091,18.624 52.091,18.624 49.333,18.646 41.039,18.959 42.039,18.959 43.039,18.959 44.039,18.959 3.56,19.02 6.56,19.02 9.56,19.02 11.06,19.02 12.56,19.02 14.06,19.02 15.56,19.02 17.06,19.02 20.06,19.02 47.06,19.02 56.06,19.02 57.56,19.02 59.06,19.02 60.56,19.02 62.06,19.02 63.56,19.02 65.641,19.054 66.641,19.054 67.641,19.054 68.641,19.054 69.641,19.054 2.708,19.088 40.543,19.309 41.543,19.309 42.543,19.309 43.543,19.309 44.543,19.309 2.359,19.584 69.9,19.577 69.55,20.073 2.708,20.088 5.81,20.52 8.81,20.52 10.31,20.52 11.81,20.52 13.31,20.52 14.81,20.52 16.31,20.52 17.81,20.52 20.81,20.52 41.81,20.52 43.31,20.52 44.81,20.52 46.31,20.52 47.81,20.52 49.31,20.52 50.81,20.52 55.31,20.52 56.81,20.52 58.31,20.52 59.81,20.52 61.31,20.52 62.81,20.52 64.31,20.52 65.81,20.52 67.31,20.52 68.81,20.52 2.359,20.584 69.9,20.577 36.092,20.629 2.708,21.088 69.55,21.073 35.803,21.478 34.677,21.518 2.359,21.584 69.9,21.577 35.307,21.828 36.307,21.828 37.307,21.828 38.307,21.828 3.56,22.02 6.56,22.02 9.56,22.02 11.06,22.02 12.56,22.02 14.06,22.02 15.56,22.02 17.06,22.02 20.06,22.02 41.06,22.02 42.56,22.02 44.06,22.02 45.56,22.02 47.06,22.02 48.56,22.02 50.06,22.02 51.56,22.02 54.56,22.02 56.06,22.02 57.56,22.02 59.06,22.02 60.56,22.02 62.06,22.02 63.56,22.02 65.06,22.02 66.56,22.02 68.06,22.02 69.55,22.073 2.708,22.088 35.803,22.178 36.803,22.178 37.803,22.178 38.803,22.178 38.298,22.527 2.359,22.584 69.9,22.577 39.115,22.714 69.55,23.073 2.708,23.088 5.81,23.52 8.81,23.52 10.31,23.52 11.81,23.52 13.31,23.52 14.81,23.52 16.31,23.52 17.81,23.52 20.81,23.52 38.81,23.52 41.81,23.52 43.31,23.52 44.81,23.52 46.31,23.52 47.81,23.52 49.31,23.52 53.81,23.52 55.31,23.52 56.81,23.52 58.31,23.52 59.81,23.52 61.31,23.52 62.81,23.52 64.31,23.52 65.81,23.52 67.31,23.52 68.81,23.52 69.9,23.577 2.359,23.584 2.708,24.088 69.55,24.073 2.359,24.584 69.9,24.577 28.667,24.762 34.09,24.82 9.56,25.02 11.06,25.02 12.56,25.02 14.06,25.02 15.56,25.02 17.06,25.02 18.56,25.02 41.06,25.02 42.56,25.02 44.06,25.02 45.56,25.02 47.06,25.02 48.56,25.02 54.56,25.02 56.06,25.02 57.56,25.02 59.06,25.02 60.56,25.02 62.06,25.02 63.56,25.02 65.06,25.02 66.56,25.02 68.06,25.02 69.55,25.073 2.708,25.088 28.37,25.352 28.949,25.352 2.359,25.584 69.9,25.577 30.221,26.01 2.708,26.088 69.55,26.073 5.81,26.52 8.81,26.52 10.31,26.52 11.81,26.52 13.31,26.52 14.81,26.52 16.31,26.52 17.81,26.52 28.31,26.52 41.81,26.52 43.31,26.52 44.81,26.52 46.31,26.52 50.81,26.52 52.31,26.52 53.81,26.52 55.31,26.52 56.81,26.52 58.31,26.52 59.81,26.52 61.31,26.52 62.81,26.52 64.31,26.52 65.81,26.52 67.31,26.52 68.81,26.52 69.9,26.577 2.359,26.584 2.708,27.088 69.55,27.073 2.359,27.584 69.9,27.577 14.06,28.02 15.56,28.02 17.06,28.02 23.06,28.02 41.06,28.02 50.06,28.02 51.56,28.02 53.06,28.02 57.56,28.02 59.06,28.02 60.56,28.02 62.06,28.02 63.56,28.02 65.06,28.02 66.56,28.02 68.06,28.02 69.55,28.073 2.708,28.088 2.359,28.584 69.9,28.577 2.708,29.088 69.55,29.073 14.81,29.52 19.31,29.52 38.81,29.52 47.81,29.52 49.31,29.52 50.81,29.52 52.31,29.52 58.31,29.52 59.81,29.52 61.31,29.52 62.81,29.52 64.31,29.52 65.81,29.52 67.31,29.52 68.81,29.52 69.9,29.577 2.359,29.584 69.55,30.073 2.708,30.088 2.359,30.584 69.9,30.577 3.56,31.02 6.56,31.02 8.06,31.02 60.56,31.02 62.06,31.02 63.56,31.02 65.06,31.02 66.56,31.02 68.06,31.02 69.55,31.073 2.708,31.088 2.359,31.584 69.9,31.577 2.708,32.088 69.55,32.073 4.31,32.52 5.81,32.52 7.31,32.52 8.81,32.52 10.31,32.52 11.81,32.52 13.31,32.52 14.81,32.52 56.81,32.52 58.31,32.52 59.81,32.52 61.31,32.52 62.81,32.52 64.31,32.52 65.81,32.52 67.31,32.52 2.359,32.584 69.9,32.577 69.302,32.726 3.246,32.803 2.708,33.088 3.371,33.345 4.371,33.345 5.371,33.345 6.371,33.345 7.371,33.345 8.371,33.345 9.371,33.345 10.371,33.345 11.371,33.345 12.371,33.345 13.371,33.345 14.371,33.345 15.371,33.345 16.371,33.345 17.371,33.345 18.371,33.345 19.371,33.345 20.371,33.345 21.371,33.345 22.371,33.345 23.371,33.345 24.371,33.345 25.371,33.349 26.371,33.349 27.371,33.349 28.371,33.349 29.371,33.349 30.371,33.349 31.371,33.349 32.371,33.349 33.371,33.349 34.371,33.349 35.371,33.349 36.371,33.349 37.371,33.349 38.371,33.349 39.371,33.349 40.371,33.349 41.371,33.349 42.371,33.349 43.371,33.349 44.371,33.349 45.371,33.349 46.371,33.349 47.371,33.349 48.371,33.349 49.371,33.349 50.371,33.349 51.371,33.349 52.371,33.349 53.371,33.349 54.371,33.346 55.371,33.345 56.371,33.345 57.371,33.345 58.371,33.345 59.371,33.345 60.371,33.345 61.371,33.345 62.371,33.345 63.371,33.345 64.371,33.345 65.371,33.345 66.371,33.345 67.371,33.345 68.371,33.345 69.371,33.345 2.867,33.695 3.867,33.695 4.867,33.695 5.867,33.695 6.867,33.695 7.867,33.695 8.867,33.695 9.867,33.695 10.867,33.695 11.867,33.695 12.867,33.695 13.867,33.695 14.867,33.695 15.867,33.695 16.867,33.695 17.867,33.695 18.867,33.695 19.867,33.695 20.867,33.695 21.867,33.695 22.867,33.695 23.867,33.695 24.867,33.695 25.867,33.695 26.867,33.695 27.867,33.695 28.867,33.695 29.867,33.695 30.867,33.695 31.867,33.695 32.867,33.695 33.867,33.695 34.867,33.695 35.867,33.695 36.867,33.695 37.867,33.695 38.867,33.695 39.867,33.695 40.867,33.695 41.867,33.695 42.867,33.695 43.867,33.695 44.867,33.695 45.867,33.695 46.867,33.695 47.867,33.695 48.867,33.695 49.867,33.695 50.867,33.695 51.867,33.695 52.867,33.695 53.867,33.695 54.867,33.695 55.867,33.695 56.867,33.695 57.867,33.695 58.867,33.695 59.867,33.695 60.867,33.695 61.867,33.695 62.867,33.695 63.867,33.695 64.867,33.695 65.867,33.695 66.867,33.695 67.867,33.695 68.867,33.695 69.867,33.695
NetC6_1: C6.1 C7.1 L1.2 U4.41 | length 9.3
  Top Layer w0.254: v1(23.24,15.66) v1(27.14,15.66) ; 26.764,15.652 U4.41@27.558,15.652 v1@27.14,15.652
  Bottom Layer w0.254: 22.344,15.57 22.434,15.66 v1(23.24,15.66) ; v1(27.14,15.66) 27.16,15.66 27.16,16.022 C7.1@27.142,16.04
  Bottom Layer w0.4: L1.2@21.046,15.108 21.881,15.108 22.344,15.57 C6.1@22.344,16.806
  Bottom Layer w0.5: L1.2@21.046,15.108 L1.2@21.098,15.16
NetC8_1: C8.1 U4.39 X1.2 | length 7.8
  Top Layer w0.254: X1.2@22.255,20.732 22.255,21.961 C8.1@22.274,21.98 ; X1.2@22.74,20.72 26.778,16.682 U4.39@27.66,16.682
NetC9_1: C9.1 U4.40 X1.1 | length 8.4
  Top Layer w0.254: X1.1@21.82,19.252 23.468,19.252 26.538,16.182 U4.40@27.66,16.182 ; X1.1@22.255,19.232 22.301,19.186 C9.1@22.301,18
NetC13_2: C13.2 C16.2 R2.1 U3.4 | length 5
  Top Layer w0.2: C16.2@52.883,14.348 52.883,15.703 U3.4@52.9,15.72
  Top Layer w0.4: C13.2@51.085,12.666 C13.2@51.085,12.612 52.886,12.612 R2.1@52.886,12.948 52.886,14.345 C16.2@52.883,14.348
NetC15_1: C15.1 C18.2 L3.1 U4.24 | length 1.9
  Top Layer w0.5: L3.1@39.511,18.724 L3.1@39.607,18.82
  Top Layer w0.7: C18.2@38.519,19.758 38.519,19.196 38.56,19.196 38.935,18.82 L3.1@39.561,18.82
NetC17_1: C17.1 C20.1 L3.2 L4.1 L6.2 | length 4.9
  Top Layer w0.7: L3.2@39.607,17.622 39.607,16.726 L6.2@39.401,16.52 C20.1@40.702,16.52 L4.1@41.914,16.52 41.919,16.525 C17.1@41.92,17.721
